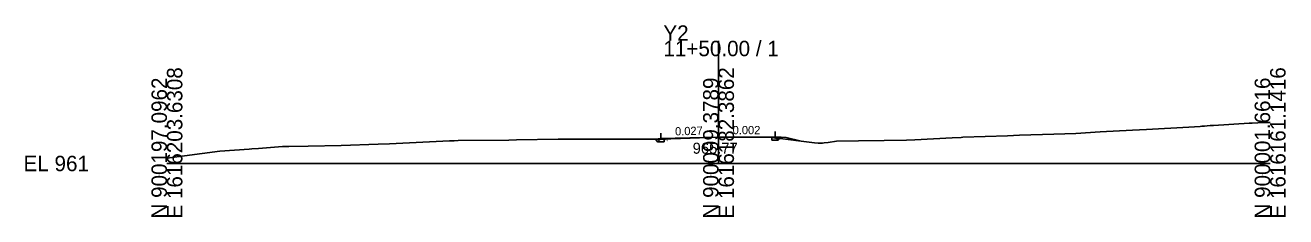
# Model space of a CAD drawing. Extents: x -26 to 1403, y -10 to 2517.
# Drawn here: x -25.7 to 202.8, y 1490.3 to 1525.1 of the extents above; entities that cross this region are included whole.
import ezdxf

# ---------------------------------------------------------------- set-up
doc = ezdxf.new("R2010")
doc.units = 0
for name, color, linetype in [('Exist Cross Section Cell', 7, 'Continuous'), ('Exist XS Center Line Elevation Label', 7, 'Continuous'), ('Exist XS Ground Line', 7, 'Continuous'), ('Prop XS Dump Level', 7, 'Continuous'), ('Prop XS Earthwork Shape', 7, 'Continuous'), ('Prop XS EOT Tick Mark', 7, 'Continuous'), ('Prop XS Finish Grade', 7, 'Continuous'), ('Prop XS Finish Grade Earthwork', 7, 'Continuous'), ('Prop XS Finish Grade Pavement', 7, 'Continuous'), ('Prop XS Pvmt Edge Slope', 7, 'Continuous'), ('Prop XS SE Text', 7, 'Continuous'), ('Prop XS Subgrade Earthwork', 7, 'Continuous')]:
    doc.layers.add(name, color=color, linetype=linetype)

msp = doc.modelspace()

# ---------------------------------------------------------------- linework, layer by layer
at = {"layer": 'Exist Cross Section Cell'}
for p, q in [((100, 1500), (100, 1522.29)), ((0, 1500), (100, 1500)), ((100, 1500), (200, 1500))]:
    msp.add_line(p, q, dxfattribs=at)
at = {"layer": 'Exist XS Ground Line'}
for p, q in [((169.18, 1505.73), (175.02, 1506.08)), ((175.02, 1506.08), (177.59, 1506.19)), ((177.59, 1506.19), (185.25, 1506.62)), ((185.25, 1506.62), (187.3, 1506.74)), ((187.3, 1506.74), (187.63, 1506.76)), ((187.63, 1506.76), (188.08, 1506.8)), ((188.08, 1506.8), (188.61, 1506.83)), ((188.61, 1506.83), (189.13, 1506.87)), ((189.13, 1506.87), (189.74, 1506.9)), ((189.74, 1506.9), (196.22, 1507.33)), ((196.22, 1507.33), (196.76, 1507.35)), ((196.76, 1507.35), (198.78, 1507.43)), ((198.78, 1507.43), (200, 1507.43)), ((40.34, 1503.57), (51.2, 1504.1)), ((51.2, 1504.1), (52.08, 1504.13)), ((52.08, 1504.13), (52.77, 1504.15)), ((52.77, 1504.15), (62, 1504.24)), ((62, 1504.24), (63.38, 1504.31)), ((63.38, 1504.31), (70.92, 1504.39)), ((70.92, 1504.39), (71.34, 1504.4)), ((71.34, 1504.4), (71.96, 1504.42)), ((71.96, 1504.42), (72.58, 1504.43)), ((72.58, 1504.43), (73.23, 1504.44)), ((73.23, 1504.44), (73.9, 1504.43)), ((73.9, 1504.43), (90.28, 1504.44)), ((90.28, 1504.44), (91.36, 1504.48)), ((91.36, 1504.48), (100.04, 1504.77)), ((100.04, 1504.77), (106.92, 1504.76)), ((106.92, 1504.76), (109.74, 1504.74)), ((109.74, 1504.74), (117.4, 1503.74)), ((119.18, 1503.73), (119.88, 1503.83)), ((119.88, 1503.83), (121.36, 1504.05)), ((121.36, 1504.05), (125.38, 1504.1)), ((125.38, 1504.1), (130.04, 1504.17)), ((130.04, 1504.17), (134.08, 1504.24)), ((134.08, 1504.24), (135.56, 1504.29)), ((135.56, 1504.29), (142.35, 1504.66)), ((142.35, 1504.66), (143.96, 1504.75)), ((143.96, 1504.75), (144.32, 1504.76)), ((144.32, 1504.76), (152.37, 1505.02)), ((152.37, 1505.02), (154.55, 1505.12)), ((154.55, 1505.12), (160.78, 1505.31)), ((160.78, 1505.31), (164.78, 1505.47)), ((164.78, 1505.47), (169.18, 1505.73)), ((0, 1500.96), (9.59, 1502.22)), ((9.59, 1502.22), (14.88, 1502.62)), ((14.88, 1502.62), (15.37, 1502.65)), ((15.37, 1502.65), (16.62, 1502.74)), ((16.62, 1502.74), (20.94, 1503.06)), ((20.94, 1503.06), (21.57, 1503.09)), ((21.57, 1503.09), (22.1, 1503.1)), ((22.1, 1503.1), (25.6, 1503.12)), ((25.6, 1503.12), (31.61, 1503.27)), ((31.61, 1503.27), (38.3, 1503.51)), ((38.3, 1503.51), (40.34, 1503.57)), ((117.4, 1503.74), (118.07, 1503.67)), ((118.07, 1503.67), (118.82, 1503.67)), ((118.82, 1503.67), (119.18, 1503.73))]:
    msp.add_line(p, q, dxfattribs=at)
at = {"layer": 'Prop XS Dump Level'}
for p, q in [((100, 1504.8), (89.54, 1504.52)), ((110.25, 1504.82), (100, 1504.8))]:
    msp.add_line(p, q, dxfattribs=at)
at = {"layer": 'Prop XS Earthwork Shape'}
for points in [[(88.94, 1503.92), (88.57, 1504.44), (89.46, 1504.44)], [(90.15, 1503.95), (89.54, 1503.94), (88.94, 1503.92), (89.46, 1504.44), (90.15, 1504.44)], [(109.69, 1504.24), (109.69, 1504.74), (109.74, 1504.74), (110.42, 1504.65), (110.83, 1504.24), (110.25, 1504.24)], [(110.42, 1504.65), (111.14, 1504.56), (110.83, 1504.24)], [(111.14, 1504.56), (114.72, 1504.09), (112.25, 1504.71), (111.35, 1504.76)]]:
    msp.add_lwpolyline(points, close=True, dxfattribs=at)
at = {"layer": 'Prop XS EOT Tick Mark'}
for p, q in [((89.54, 1504.52), (89.54, 1505.52)), ((110.25, 1504.82), (110.25, 1505.82))]:
    msp.add_line(p, q, dxfattribs=at)
at = {"layer": 'Prop XS Finish Grade'}
for p, q in [((89.54, 1504.52), (88.57, 1504.44)), ((110.25, 1504.82), (111.35, 1504.76))]:
    msp.add_line(p, q, dxfattribs=at)
at = {"layer": 'Prop XS Finish Grade Earthwork'}
for p, q in [((111.35, 1504.76), (112.25, 1504.71)), ((112.25, 1504.71), (114.72, 1504.09))]:
    msp.add_line(p, q, dxfattribs=at)
at = {"layer": 'Prop XS Finish Grade Pavement'}
for p, q in [((89.54, 1504.52), (100, 1504.8)), ((100, 1504.8), (110.25, 1504.82))]:
    msp.add_line(p, q, dxfattribs=at)
at = {"layer": 'Prop XS Pvmt Edge Slope'}
for p, q in [((89.54, 1504.52), (88.94, 1503.92)), ((110.25, 1504.82), (110.83, 1504.24))]:
    msp.add_line(p, q, dxfattribs=at)
at = {"layer": 'Prop XS Subgrade Earthwork'}
for p, q in [((88.94, 1503.92), (88.57, 1504.44)), ((89.54, 1503.94), (88.94, 1503.92)), ((90.15, 1503.95), (89.54, 1503.94)), ((90.15, 1503.95), (90.15, 1504.44)), ((109.69, 1504.24), (109.69, 1504.74)), ((109.69, 1504.24), (110.25, 1504.24)), ((110.25, 1504.24), (110.83, 1504.24)), ((110.83, 1504.24), (111.35, 1504.76))]:
    msp.add_line(p, q, dxfattribs=at)

# ---------------------------------------------------------------- texts
at = {"layer": 'Exist Cross Section Cell'}
for s, p in [('Y2', (90, 1522.29)), ('11+50.00 / 1', (90, 1519.49)), ('EL 961', (-26, 1498.6))]:
    msp.add_text(s, height=2.8, dxfattribs=at).set_placement(p)
for s, p in [('N 900197.0962', (0, 1490)), ('E 1616203.6308', (2.8, 1490)), ('N 900099.3789', (100, 1490)), ('E 1616182.3862', (102.8, 1490)), ('N 900001.6616', (200, 1490)), ('E 1616161.1416', (202.8, 1490))]:
    msp.add_text(s, height=2.8, rotation=90, dxfattribs=at).set_placement(p)
at = {"layer": 'Exist XS Center Line Elevation Label'}
msp.add_text('965.77', height=2, dxfattribs=at).set_placement((95.31, 1501.77))
at = {"layer": 'Prop XS Dump Level'}
for s, height, p in [('Case1', 0.04, (86.54, 1504.24)), ('Eop', 0.3, (90.15, 1504.14)), ('Eop', 0.3, (109.69, 1504.44)), ('Case1', 0.04, (113.25, 1504.61))]:
    msp.add_text(s, height=height, dxfattribs=at).set_placement(p)
at = {"layer": 'Prop XS SE Text'}
for s, rotation, p in [('0.027', 1.5533, (92.14, 1505.09)), ('0.002', 0.1074, (102.56, 1505.31))]:
    msp.add_text(s, height=1.5, rotation=rotation, dxfattribs=at).set_placement(p)

doc.saveas('drawing.dxf')
